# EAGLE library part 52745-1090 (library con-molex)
FFC/FPC-to-Board 0.50mm (.020") SMT Top Contact Right Angle, ZIF, Style Receptacle 52745 / 52435 Source: http://www.molex.com/product/ffc/52745.html
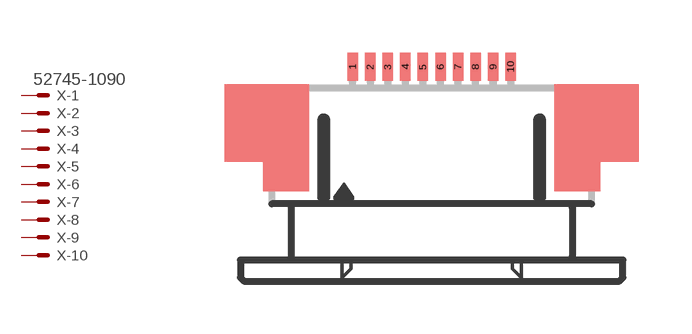
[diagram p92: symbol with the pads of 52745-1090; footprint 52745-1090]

Designator prefix X; gates -1=MV -2=M -3=M -4=M -5=M -6=M -7=M -8=M -9=M -10=M

## 52745-1090 (MPN: 52745-1090; OC_FARNELL: unknown; OC_NEWARK: 92M6380)  [52745-1090]
1  -1:S  pas
2  -2:S  pas
3  -3:S  pas
4  -4:S  pas
5  -5:S  pas
6  -6:S  pas
7  -7:S  pas
8  -8:S  pas
9  -9:S  pas
10  -10:S  pas

## Footprint 52745-1090 (pad centres in mm)
FFC/FPC-to-Board 0.50mm (.020") SMT Top Contact Right Angle, ZIF, Style Receptacle 52745 / 52435 Source: http://www.molex.com/product/ffc/52745.html
smd 0.3 x 0.8: 1 -2.25,2.5; 2 -1.75,2.5; 3 -1.25,2.5; 4 -0.75,2.5; 5 -0.25,2.5; 6 0.25,2.5; 7 0.75,2.5; 8 1.25,2.5; 9 1.75,2.5; 10 2.25,2.5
